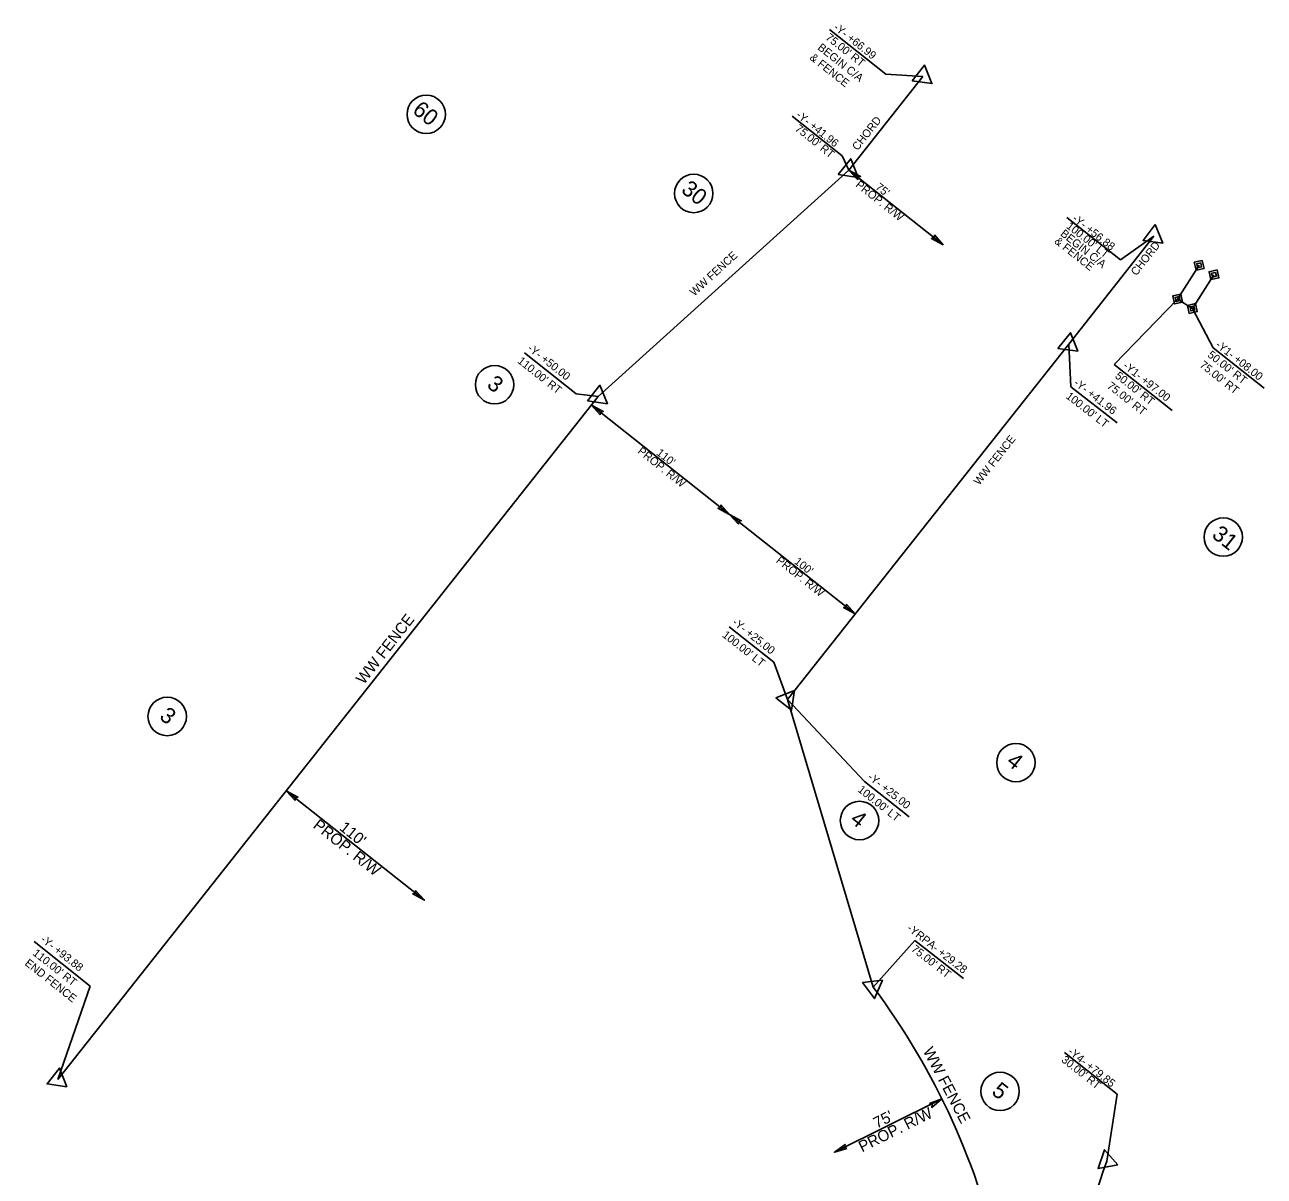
# Model space of a CAD drawing. Extents: x 1779796 to 1783527, y 810952 to 815815.
# Drawn here: x 1781911 to 1782685, y 813658 to 814376 of the extents above; entities that cross this region are included whole.
import ezdxf

# ---------------------------------------------------------------- set-up
doc = ezdxf.new("R2010")
doc.units = 0
for name, color, linetype in [('Prop Dimension', 7, 'Continuous'), ('Prop Dimension Text', 7, 'Continuous'), ('Prop Easement Permanent Utility', 7, 'Continuous'), ('Prop Easement Permanent Utility Station Offsets', 7, 'Continuous'), ('Prop Fence Woven Wire', 7, 'Continuous'), ('Prop Parcel Number CELL', 7, 'Continuous'), ('Prop Parcel Number Text', 7, 'Continuous'), ('Prop ROW Marker CELL', 7, 'Continuous'), ('Prop ROW Permanent Easement CELL', 7, 'Continuous'), ('Prop ROW RW CA Lines', 7, 'Continuous'), ('Prop ROW RW Lines', 7, 'Continuous'), ('Prop ROW Station Offsets', 7, 'Continuous'), ('Prop Terminator CELL', 7, 'Continuous')]:
    doc.layers.add(name, color=color, linetype=linetype)

msp = doc.modelspace()

# ---------------------------------------------------------------- linework, layer by layer
at = {"layer": 'Prop Dimension'}
for p, q in [((1782425.3, 814285.69), (1782484.1, 814239.13)), ((1782350.75, 814070.69), (1782264.51, 814138.97)), ((1782429.15, 814008.62), (1782350.75, 814070.69)), ((1782073.87, 813898.18), (1782160.11, 813829.9)), ((1782483.37, 813705.76), (1782416.16, 813672.47))]:
    msp.add_line(p, q, dxfattribs=at)
at = {"layer": 'Prop Easement Permanent Utility'}
for p, q in [((1782644, 814226.29), (1782630.54, 814205.23)), ((1782639.8, 814199.3), (1782653.27, 814220.37)), ((1782630.54, 814205.23), (1782639.8, 814199.3))]:
    msp.add_line(p, q, dxfattribs=at)
at = {"layer": 'Prop Easement Permanent Utility Station Offsets'}
for p, q in [((1782684.63, 814149.5), (1782652.85, 814174.66)), ((1782627.11, 814135.73), (1782590.88, 814164.41))]:
    msp.add_line(p, q, dxfattribs=at)
for points in [[(1782590.88, 814164.41), (1782630.54, 814205.23)], [(1782652.85, 814174.66), (1782639.8, 814199.3)]]:
    msp.add_lwpolyline(points, dxfattribs=at)
at = {"layer": 'Prop Fence Woven Wire'}
for p, q in [((1782471.44, 814344.2), (1782425.3, 814285.69)), ((1782425.3, 814285.69), (1782268.73, 814144.31)), ((1782615.63, 814244.52), (1782562.51, 814177.06)), ((1782562.51, 814177.06), (1782386.82, 813955.15)), ((1782268.73, 814144.31), (1781931.12, 813717.88)), ((1782386.82, 813955.15), (1782440.43, 813775.63))]:
    msp.add_line(p, q, dxfattribs=at)
msp.add_arc((1782080.1, 813506.06), 450, 11.98935, 36.80105, dxfattribs=at)
at = {"layer": 'Prop Parcel Number CELL'}
for p, q in [((1782161.24, 814320.53), (1782161.24, 814320.53)), ((1782328.33, 814271.14), (1782328.33, 814271.14)), ((1782203.95, 814151.72), (1782203.95, 814151.72)), ((1782659.04, 814056.58), (1782659.04, 814056.58)), ((1781999.46, 813944.59), (1781999.46, 813944.59)), ((1782529.54, 813915.78), (1782529.54, 813915.78)), ((1782431.88, 813879.61), (1782431.88, 813879.61)), ((1782519.68, 813710.5), (1782519.68, 813710.5))]:
    msp.add_line(p, q, dxfattribs=at)
for centre in [(1782161.24, 814320.53), (1782328.33, 814271.14), (1782203.95, 814151.72), (1782659.04, 814056.58), (1781999.46, 813944.59), (1782529.54, 813915.78), (1782431.88, 813879.61), (1782519.68, 813710.5)]:
    msp.add_circle(centre, 12, dxfattribs=at)
at = {"layer": 'Prop ROW Marker CELL'}
for p, q in [((1782471.44, 814344.2), (1782471.44, 814344.2)), ((1782425.3, 814285.69), (1782425.3, 814285.69)), ((1782615.63, 814244.52), (1782615.63, 814244.52)), ((1782644, 814226.29), (1782644, 814226.29)), ((1782653.27, 814220.37), (1782653.27, 814220.37)), ((1782630.54, 814205.23), (1782630.54, 814205.23)), ((1782639.8, 814199.3), (1782639.8, 814199.3)), ((1782562.51, 814177.06), (1782562.51, 814177.06)), ((1782268.73, 814144.31), (1782268.73, 814144.31)), ((1782386.82, 813955.15), (1782386.82, 813955.15)), ((1782440.43, 813775.63), (1782440.43, 813775.63)), ((1781931.12, 813717.88), (1781931.12, 813717.88)), ((1782586.31, 813666.98), (1782586.31, 813666.98))]:
    msp.add_line(p, q, dxfattribs=at)
for points in [[(1782464.74, 814341.52), (1782472.45, 814351.33), (1782477.12, 814339.76)], [(1782418.59, 814283.04), (1782426.36, 814292.81), (1782430.96, 814281.21)], [(1782616.63, 814251.66), (1782621.31, 814240.09), (1782608.95, 814241.8)], [(1782555.8, 814174.42), (1782563.56, 814184.18), (1782568.16, 814172.58)], [(1782262.02, 814141.66), (1782269.78, 814151.43), (1782274.38, 814139.83)], [(1782379.68, 813956.21), (1782391.29, 813960.8), (1782389.48, 813948.45)], [(1782433.8, 813778.48), (1782446.19, 813779.94), (1782441.29, 813768.47)], [(1781936.78, 813713.41), (1781924.43, 813715.22), (1781932.16, 813725.02)], [(1782593.12, 813664.6), (1782580.86, 813662.27), (1782584.94, 813674.06)]]:
    msp.add_lwpolyline(points, close=True, dxfattribs=at)
at = {"layer": 'Prop ROW Permanent Easement CELL'}
for points in [[(1782645.94, 814229.32), (1782647.04, 814224.35), (1782642.06, 814223.26), (1782640.97, 814228.23)], [(1782644.97, 814227.81), (1782645.52, 814225.32), (1782643.03, 814224.78), (1782642.49, 814227.26)], [(1782655.21, 814223.4), (1782656.3, 814218.43), (1782651.33, 814217.33), (1782650.24, 814222.31)], [(1782654.24, 814221.88), (1782654.79, 814219.4), (1782652.3, 814218.85), (1782651.75, 814221.34)], [(1782632.47, 814208.26), (1782633.57, 814203.29), (1782628.6, 814202.2), (1782627.5, 814207.17)], [(1782631.51, 814206.75), (1782632.05, 814204.26), (1782629.57, 814203.71), (1782629.02, 814206.2)], [(1782641.74, 814202.34), (1782642.84, 814197.36), (1782637.86, 814196.27), (1782636.77, 814201.24)], [(1782640.77, 814200.82), (1782641.32, 814198.33), (1782638.83, 814197.79), (1782638.29, 814200.27)]]:
    msp.add_lwpolyline(points, close=True, dxfattribs=at)
at = {"layer": 'Prop ROW RW CA Lines'}
for p, q in [((1782425.3, 814285.69), (1782471.44, 814344.2)), ((1782268.73, 814144.31), (1782425.3, 814285.69)), ((1782562.51, 814177.06), (1782615.63, 814244.52)), ((1782386.82, 813955.15), (1782562.51, 814177.06)), ((1781931.12, 813717.88), (1782268.73, 814144.31)), ((1782386.82, 813955.15), (1782440.43, 813775.63))]:
    msp.add_line(p, q, dxfattribs=at)
msp.add_arc((1782080.1, 813506.06), 450, 11.98935, 36.80105, dxfattribs=at)
at = {"layer": 'Prop ROW RW Lines'}
msp.add_arc((1783464.56, 813361.08), 930, 160.79649, 173.99833, dxfattribs=at)
at = {"layer": 'Prop ROW Station Offsets'}
for p, q in [((1782448.37, 814345.58), (1782413.19, 814373.43)), ((1782420.98, 814294.64), (1782389.88, 814319.43)), ((1782425.3, 814285.69), (1782420.98, 814294.64)), ((1782594.83, 814229.6), (1782561.33, 814256.12)), ((1782562.51, 814177.06), (1782563.86, 814150.48)), ((1782254.85, 814146.08), (1782222.55, 814171.65)), ((1782268.73, 814144.31), (1782254.85, 814146.08)), ((1782563.86, 814150.48), (1782592.75, 814128.03)), ((1782378.31, 813978.48), (1782350.4, 814000.58)), ((1782386.82, 813955.15), (1782378.31, 813978.48)), ((1782435.02, 813903.96), (1782386.82, 813955.15)), ((1782462.93, 813881.86), (1782435.02, 813903.96)), ((1781951.35, 813776.28), (1781916.29, 813804.05)), ((1782440.43, 813775.63), (1782466.37, 813804.81)), ((1782466.37, 813804.81), (1782496.85, 813781.05)), ((1781931.12, 813717.88), (1781951.35, 813776.28)), ((1782592.72, 813708.75), (1782559.96, 813734.7)), ((1782586.31, 813666.98), (1782592.72, 813708.75))]:
    msp.add_line(p, q, dxfattribs=at)
for points in [[(1782448.37, 814345.58), (1782471.44, 814344.2)], [(1782594.83, 814229.6), (1782615.63, 814244.52)]]:
    msp.add_lwpolyline(points, dxfattribs=at)
at = {"layer": 'Prop Terminator CELL'}
for points in [[(1782430.79, 814279.57), (1782425.3, 814285.69), (1782432.58, 814281.76), (1782430.88, 814281.27)], [(1782478.62, 814245.25), (1782484.1, 814239.13), (1782476.82, 814243.06), (1782478.53, 814243.55)], [(1782269.99, 814132.85), (1782264.51, 814138.97), (1782271.78, 814135.05), (1782270.08, 814134.56)], [(1782345.26, 814076.82), (1782350.75, 814070.69), (1782343.47, 814074.62), (1782345.17, 814075.11)], [(1782356.23, 814064.57), (1782350.75, 814070.69), (1782358.03, 814066.77), (1782356.32, 814066.28)], [(1782423.67, 814014.74), (1782429.15, 814008.62), (1782421.87, 814012.55), (1782423.58, 814013.04)], [(1782079.35, 813892.06), (1782073.87, 813898.18), (1782081.15, 813894.25), (1782079.44, 813893.77)], [(1782154.63, 813836.02), (1782160.11, 813829.9), (1782152.83, 813833.83), (1782154.54, 813834.31)], [(1782475.61, 813703.03), (1782483.37, 813705.76), (1782476.96, 813700.53), (1782477.16, 813702.29)], [(1782424.03, 813674.82), (1782416.16, 813672.47), (1782422.82, 813677.38), (1782422.53, 813675.63)]]:
    msp.add_lwpolyline(points, close=True, dxfattribs=at)

# ---------------------------------------------------------------- texts
at = {"layer": 'Prop Dimension Text'}
for s, height, rotation, p in [('PROP. R/W', 5, 321.52512, (1782428.97, 814275.78)), ("75' ", 5, 321.52512, (1782441.37, 814274.29)), ('WW FENCE', 5, 42.46494, (1782328.65, 814206.74)), ('PROP. R/W', 5, 321.52512, (1782292.82, 814109.42)), ('WW FENCE', 5, 51.63659, (1782506.65, 814088.6)), ("110' ", 5, 321.52512, (1782304.62, 814108.42)), ('PROP. R/W', 5, 321.52512, (1782379.37, 814041.18)), ("100' ", 5, 321.52512, (1782390.7, 814040.55)), ('WW FENCE', 7, 52.02128, (1782122.32, 813964.14)), ('PROP. R/W', 7, 321.52512, (1782090.04, 813875.59)), ("110' ", 7, 321.52512, (1782106.55, 813874.19)), ('WW FENCE', 7, 297.61891, (1782471.31, 813735.88)), ('PROP. R/W', 7, 26.52492, (1782433.48, 813672.34)), ("75' ", 7, 26.52492, (1782442.71, 813687.2))]:
    msp.add_text(s, height=height, rotation=rotation, dxfattribs=at).set_placement(p)
at = {"layer": 'Prop Easement Permanent Utility Station Offsets'}
for s, p in [('-Y1- +08.00', (1782653.8, 814175.83)), ("50.00' RT", (1782648.83, 814169.56)), ("50.00' RT", (1782591.05, 814156.41)), ('-Y1- +97.00', (1782596.01, 814162.69)), ("75.00' RT", (1782643.86, 814163.28)), ("75.00' RT", (1782586.08, 814150.14))]:
    msp.add_text(s, height=5, rotation=321.63093, dxfattribs=at).set_placement(p)
at = {"layer": 'Prop Parcel Number Text'}
for s, p in [('60', (1782152.03, 814321.91)), ('30', (1782319.88, 814272.35)), ('3', (1782198.5, 814150.68)), ('31', (1782651.32, 814056.92)), ('3', (1781994.02, 813943.56)), ('4', (1782523.03, 813915.22)), ('4', (1782425.38, 813879.05)), ('5', (1782513.78, 813709.3))]:
    msp.add_text(s, height=10, rotation=321.63093, dxfattribs=at).set_placement(p)
at = {"layer": 'Prop ROW RW Lines'}
for s, p in [('-Y4- +79.85', (1782561.62, 813734.53)), ("30.00' RT", (1782557.55, 813729.39))]:
    msp.add_text(s, height=5, rotation=321.61668, dxfattribs=at).set_placement(p)
at = {"layer": 'Prop ROW Station Offsets'}
for s, rotation, p in [('-Y- +66.99', 321.63093, (1782415.22, 814374)), ("75.00' RT", 321.63093, (1782410.25, 814367.73)), ('BEGIN C/A', 321.63093, (1782405.28, 814361.46)), ('& FENCE', 321.63093, (1782400.32, 814355.18)), ("75.00' RT", 321.43719, (1782391.2, 814310.8)), ('-Y- +41.96', 321.43719, (1782391.81, 814319.29)), ('CHORD', 51.77995, (1782430.69, 814297.55)), ("100.00' LT", 321.63093, (1782560.64, 814249.95)), ('-Y- +56.88', 321.63093, (1782564.36, 814254.65)), ('BEGIN C/A', 321.63093, (1782556.92, 814245.24)), ('& FENCE', 321.63093, (1782553.19, 814240.54)), ('CHORD', 51.77995, (1782604.78, 814219.4)), ('-Y- +50.00', 321.63093, (1782224.11, 814173.61)), ("110.00' RT", 321.63093, (1782217.9, 814165.77)), ('-Y- +41.96', 322.15226, (1782565.26, 814152.01)), ("100.00' LT", 322.15226, (1782560.32, 814143.74)), ('-Y- +25.00', 321.63093, (1782351.96, 814002.54)), ("100.00' LT", 321.63093, (1782345.75, 813994.7)), ('-Y- +25.00', 321.63093, (1782436.57, 813905.92)), ("100.00' LT", 321.63093, (1782430.36, 813898.08)), ('-YRPA- +29.28', 322.05456, (1782461.09, 813811.49)), ('-Y- +93.88', 321.61668, (1781919.93, 813804.59)), ("110.00' RT", 321.61668, (1781915.06, 813796.03)), ("75.00' RT", 322.05456, (1782463.79, 813798.58)), ('END FENCE', 321.61668, (1781910.09, 813789.76))]:
    msp.add_text(s, height=5, rotation=rotation, dxfattribs=at).set_placement(p)

doc.saveas('drawing.dxf')
